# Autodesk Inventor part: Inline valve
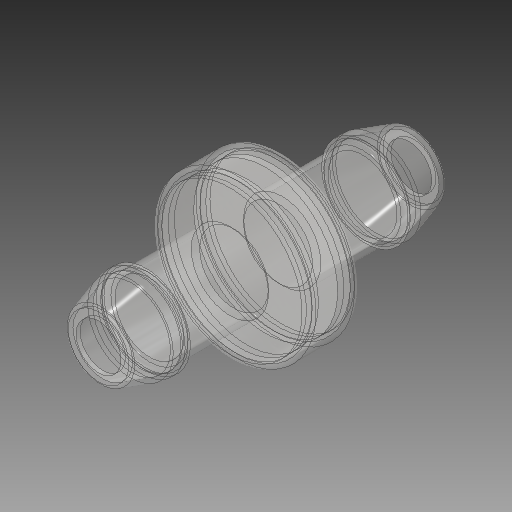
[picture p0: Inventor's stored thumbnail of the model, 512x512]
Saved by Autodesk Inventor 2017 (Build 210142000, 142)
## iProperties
Created: 2020-03
Part Number: Inline valve
Material: Polycarbonate, Clear
Document SubType Name: Modeling
Designer: user
Density: 1.2 g/cm^3
Appearance: Polycarbonate - Clear
Mass: 19.4314 g
Surface Area: 250.414 cm^2
Volume: 16.1928 cm^3
Author: user
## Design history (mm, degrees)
sketch "Sketch1"
  geometry: L1 (6.465, 0)-(8.681, 0); L2 (11.059, -37.6)-(20.7, -37.6); L3 (22.7, -39.6)-(22.7, -50.6); L4 (20.7, -52.6)-(11.059, -52.6); L5 (8.681, -90.177)-(6.465, -90.177); L6 (9.636, -0.704)-(12.251, -9.128); L7 (12.7, -13.598)-(12.059, -13.598); L8 (11.059, -14.598)-(11.059, -37.6); L9 (9.636, -89.473)-(12.7, -79.601); L10 (12.7, -76.579)-(12.059, -76.579); L11 (11.059, -75.579)-(11.059, -52.6); L12 (12.7, -12.092)-(12.7, -13.598); L13 (12.7, -76.579)-(12.7, -79.601); L14 (21.5, -50.6)-(21.5, -39.6); L15 (20.7, -38.8)-(9.859, -38.8); L16 (9.859, -38.8)-(9.859, -14.598); L17 (11.5, -12.47)-(11.5, -12.092); L18 (11.105, -9.484)-(8.534, -1.2); L19 (8.534, -1.2)-(6.465, -1.2); L20 (6.465, -88.977)-(8.534, -88.977); L21 (8.534, -88.977)-(11.5, -79.419); L22 (11.5, -79.419)-(11.5, -77.707); L23 (9.859, -75.579)-(9.859, -51.4); L24 (9.859, -51.4)-(20.7, -51.4); L25 (6.465, 0)-(6.465, -1.2); L26 (6.465, -88.977)-(6.465, -90.177); L27 (0, -108.432)-(0, 18.255) reference; A1 r 2 centre (20.7, -39.6) between (22.7, -39.6) and (20.7, -37.6); A2 r 2 centre (20.7, -50.6) between (20.7, -52.6) and (22.7, -50.6); A3 r 10 centre (2.7, -12.092) between (12.7, -12.092) and (12.251, -9.128); A4 r 1 centre (12.059, -14.598) between (12.059, -13.598) and (11.059, -14.598); A5 r 1 centre (12.059, -75.579) between (11.059, -75.579) and (12.059, -76.579); A6 r 1 centre (8.681, -89.177) between (8.681, -90.177) and (9.636, -89.473); A7 r 1 centre (8.681, -1) between (9.636, -0.704) and (8.681, 0); A8 r 0.8 centre (20.7, -39.6) between (21.5, -39.6) and (20.7, -38.8); A9 r 2.2 centre (12.059, -14.598) between (11.5, -12.47) and (9.859, -14.598); A10 r 8.8 centre (2.7, -12.092) between (11.5, -12.092) and (11.105, -9.484); A11 r 2.2 centre (12.059, -75.579) between (9.859, -75.579) and (11.5, -77.707); A12 r 0.8 centre (20.7, -50.6) between (20.7, -51.4) and (21.5, -50.6); 1 further point
  constraints: 52 end point, 24 point on circle, 13 tangent, 12 centre point, 6 perpendicular, 4 equal radius, 2 vertical, 1 horizontal, 8 other
  dimensions: "d5" = 2 radius of A1 (derived); "d6" = 10 radius of A3 (derived); "d7" = 1 radius of A4; "d8" = 1.2 distance between parallel lines of L3 L14
revolve "Revolution2" sketch "Sketch1" stored, may be unused: angle "d11" = 90 deg
sketch "Sketch2"
  geometry: L1 (0, -40.574)-(20.612, -40.574); L2 (20.612, -40.574)-(20.612, -42.338); L3 (20.612, -42.338)-(0, -42.338); L4 (0, -42.338)-(0, -40.574); L5 (0, -49.626)-(20.612, -49.626); L6 (20.612, -49.626)-(20.612, -47.862); L7 (20.612, -47.862)-(0, -47.862); L8 (0, -47.862)-(0, -49.626); 1 further point
  constraints: 16 end point, 3 perpendicular, 1 horizontal
revolve "Revolution3" sketch "Sketch2" stored, may be unused: angle "d12" = 90 deg
body "Solid2"
